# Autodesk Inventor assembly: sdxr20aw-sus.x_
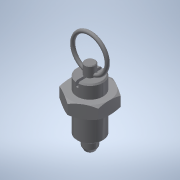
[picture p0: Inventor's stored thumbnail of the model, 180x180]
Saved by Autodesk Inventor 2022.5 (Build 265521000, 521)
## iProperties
Part Number: sdxr20aw-sus.x_
Material: 一般
Document SubType Name: Assembly
Designer: ImaoCorp
Sending System: SOLIDWORKS 2017-2017317
MC: AMD64
MC_MODEL: Intel64 Family 6 Model 60 Stepping 3, GenuineIntel
OS: Windows_NT
FRU: Parasolid Version 29.0, build 201,  4-17-2017
FORMAT: text
GUISE: transmit
KEY: sdxr20aw-sus
FILE: sdxr20aw-sus.x_t
DATE: Wed Sep 18 16:15:29 2019
Author: ImaoCorp
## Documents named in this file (3)
- X:\14_SW2022-Inv2022\00_全2023-1023新製品(TCC)まで\s\sdxr20aw-sus\SDXR20AW-SUS.iam
- X:\14_SW2022-Inv2022\00_全2023-1023新製品(TCC)まで\s\sdxr20aw-sus\sdxr20aw-sus_01.ipt
- X:\14_SW2022-Inv2022\00_全2023-1023新製品(TCC)まで\s\sdxr20aw-sus\sdxr20aw-sus_02.ipt
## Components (2 placed, 2 different names)
1. sdxr20aw-sus_01
2. sdxr20aw-sus_02
